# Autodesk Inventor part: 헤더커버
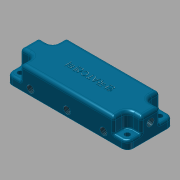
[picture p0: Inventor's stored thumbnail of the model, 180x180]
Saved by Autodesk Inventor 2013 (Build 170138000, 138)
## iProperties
Created: 2015-11
Part Number: 헤더커버
Material: 알루미늄 6061
Document SubType Name: Modeling
Designer: mduedu
Density: 2.71 g/cm^3
Mass: 171.744 g
Surface Area: 160.864 cm^2
Volume: 63.3741 cm^3
Author: mduedu
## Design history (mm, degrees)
sketch "스케치1"
  geometry: L1 (52.5, 20)-(-52.5, 20); L2 (-52.5, 20)-(-52.5, -20); L3 (-52.5, -20)-(52.5, -20); L4 (52.5, -20)-(52.5, 20); L5 (52.5, 20)-(-52.5, -20); L6 (-52.5, 20)-(52.5, -20); 1 further point
  constraints: 12 end point, 2 midpoint, 2 parallel, 1 horizontal, 1 perpendicular
  dimensions: "d0" = 105 distance of L3.end L2.end; "d1" = 40 distance of L2.end L1.end
extrude "돌출1" new body sketch "스케치1" distance "d2" = 20; taper "d3" = 0 deg
sketch "스케치2"
  geometry: L1 (-52.5, -20)-(-52.5, 20) reference; L2 (-52.5, 20)-(52.5, 20) reference; L3 (52.5, 20)-(52.5, -20) reference; L4 (52.5, -20)-(-52.5, -20) reference; L5 (-52.5, 20)-(-40.5, 20); L6 (-40.5, 20)-(-40.5, 8); L7 (-40.5, 8)-(-52.5, 8); L8 (-52.5, 8)-(-52.5, 20); L9 (52.5, 20)-(40.5, 20); L10 (40.5, 20)-(40.5, 8); L11 (40.5, 8)-(52.5, 8); L12 (52.5, 8)-(52.5, 20); L13 (52.5, -20)-(40.5, -20); L14 (40.5, -20)-(40.5, -8); L15 (40.5, -8)-(52.5, -8); L16 (52.5, -8)-(52.5, -20); L17 (-52.5, -20)-(-40.5, -20); L18 (-40.5, -20)-(-40.5, -8); L19 (-40.5, -8)-(-52.5, -8); L20 (-52.5, -8)-(-52.5, -20); 1 further point
  constraints: 32 end point, 8 parallel, 6 equal length, 4 horizontal, 4 perpendicular
  dimensions: "d4" = 12 distance of L6.end L7.end; "d5" = 12 distance of L5.end L6.end
extrude "돌출2" cut sketch "스케치2" distance "d6" = 13; taper "d7" = 0 deg
fillet "모깎기1" dims "d8" = 5
fillet "모깎기2" dims "d9" = 1
fillet "모깎기3" dims "d10" = 5
fillet "모깎기4" dims "d11" = 2
fillet "모깎기5" dims "d12" = 3
sketch "스케치3"
  geometry: L1 (-46.5, -14)-(46.5, -14); L2 (46.5, -14)-(46.5, 14); L3 (46.5, 14)-(-46.5, 14); L4 (-46.5, 14)-(-46.5, -14); L5 (-46.5, -14)-(46.5, 14); L6 (46.5, -14)-(-46.5, 14); L7 (47.5, 20)-(-47.5, 20) reference; L8 (52.5, -15)-(52.5, 15) reference; 5 further points
  constraints: 12 end point, 4 coincident, 2 midpoint, 2 parallel, 1 horizontal, 1 perpendicular
  dimensions: "d13" = 6 distance between parallel lines of L3 L7; "d14" = 6 distance between parallel lines of L2 L8
hole "구멍1" sketch "스케치3" at (-46.5, 14), (46.5, 14), (46.5, -14), (-46.5, -14) diameter "d15" = 4.5; stored, may be unused: countersink angle "d19" = 90 deg, drill point angle "d21" = 118 deg; dims "d16" = 6, "d17" = 4, "d18" = 2, "d20" = 8
sketch "스케치4"
  geometry: L1 (47.5, -20)-(-47.5, -20) reference; L2 (52.5, 15)-(52.5, -15) reference; L3 (-47.5, 20)-(47.5, 20) reference; L4 (-52.5, -15)-(-52.5, 15) reference; L5 (-52.5, 0)-(52.5, 0); C1 r 12.25 at (0, 0); C2 r 2.25 at (46.5, 14) reference; C3 r 2.25 at (-46.5, -14) reference; C4 r 2.25 at (46.5, -14) reference; C5 r 2.25 at (-46.5, 14) reference; C6 r 12.25 at (-32, 0); C7 r 12.25 at (32, 0); A1 r 5 centre (-47.5, -15) between (-52.5, -15) and (-47.5, -20) reference; A2 r 5 centre (47.5, -15) between (47.5, -20) and (52.5, -15) reference; A3 r 5 centre (47.5, 15) between (52.5, 15) and (47.5, 20) reference; A4 r 5 centre (-47.5, 15) between (-47.5, 20) and (-52.5, 15) reference; 1 further point
  constraints: 3 centre point, 2 end point, 2 midpoint, 2 point on line, 1 coincident
  dimensions: "d22" = 24.5 diameter of C1; "d23" = 24.5 diameter of C7 (= d22); "d24" = 24.5 diameter of C6 (= d22); "d25" = 32 distance of point (0, 0) C6.centre; "d26" = 32 distance of C7.centre point (0, 0) (= d25)
extrude "돌출3" cut sketch "스케치4" distance "d27" = 8; taper "d28" = 0 deg
fillet "모깎기6" dims "d29" = 5
sketch "스케치5"
  geometry: L1 (-52.5, 12)-(-47.119, 12); L2 (-40.191, 8)-(-37.635, 3.574); L3 (-52.5, 17)-(-52.5, 8) reference; L4 (-47.5, 0)-(-52.5, 0) reference; L5 (37.5, 20)-(-37.5, 20) reference; L6 (0, 0)-(0, 20); L7 (52.5, 12)-(47.119, 12); L8 (40.191, 8)-(37.635, 3.574); A1 r 8 centre (-47.119, 4) between (-40.191, 8) and (-47.119, 12); A2 r 8 centre (47.119, 4) between (47.119, 12) and (40.191, 8); 1 further point
  constraints: 10 end point, 5 symmetric about line, 4 point on circle, 3 point on line, 2 centre point, 2 tangent, 1 horizontal, 1 midpoint, 1 other
  dimensions: "d30" = 10 distance of L1.start point (-42.5, 12); "d32" = 120 deg angle of L2 L1; "d34" = 12 distance between parallel lines of L1 L4; "d35" = 8 radius of A1
sketch "스케치6"
  geometry: L1 (20, -5)-(20, 5) reference; L2 (8, -20)-(17, -20) reference; L3 (12, -20)-(12, -14.619); L4 (8, -7.691)-(3.81, -5.272); L5 (0, -20)-(0, -15) reference; A1 r 8 centre (4, -14.619) between (12, -14.619) and (8, -7.691); 2 further points
  constraints: 4 end point, 3 point on line, 2 point on circle, 2 tangent, 1 centre point, 1 perpendicular
  dimensions: "d36" = 10 distance of L3.start point (12, -10); "d38" = 12 distance between parallel lines of L3 L5; "d39" = 120 deg angle of L3 L4; "d40" = 8 radius of A1
node "작업점1"
node "작업점2"
node "작업점3"
hole "구멍2" diameter "d43" = 5.944; stored, may be unused: countersink angle "d49" = 90 deg, drill point angle "d51" = 0 deg; dims "d41" = 10, "d42" = 10, "d44" = 6.886, "d45" = 0.62479, "d46" = 5.959, "d47" = 4, "d48" = 2, "d50" = 6.9
hole "구멍3" diameter "d54" = 5.944; stored, may be unused: countersink angle "d60" = 90 deg, drill point angle "d62" = 0 deg; dims "d52" = 10, "d53" = 10, "d55" = 6.886, "d56" = 0.62479, "d57" = 5.959, "d58" = 4, "d59" = 2, "d61" = 6.9
hole "구멍4" diameter "d65" = 5.944; stored, may be unused: countersink angle "d71" = 90 deg, drill point angle "d73" = 0 deg; dims "d63" = 10, "d64" = 10, "d66" = 6.886, "d67" = 0.62479, "d68" = 5.959, "d69" = 4, "d70" = 2, "d72" = 6.9
sketch "스케치7"
  geometry: C1 r 2.972 at (15, 12) reference; 1 further point
sketch "스케치8"
  geometry: C1 r 2.972 at (15, 12) reference; 1 further point
sketch "스케치9"
  geometry: C1 r 2.972 at (47.5, 12) reference; 1 further point
feature "스윕1" dims "d74" = 0
feature "스윕2" dims "d75" = 0
feature "스윕3" dims "d76" = 0
sketch "스케치10"
  geometry: L1 (0, 0)-(95, 0) reference; L2 (22.75, 8)-(8.768, 8) reference; L3 (54.75, 8)-(40.25, 8) reference; L4 (86.232, 8)-(72.25, 8) reference; L5 (15.759, 8)-(15.759, 0); L6 (47.5, 8)-(47.5, 0); L7 (79.241, 8)-(79.241, 0); 5 further points
  constraints: 6 end point, 5 point on line, 3 midpoint, 2 horizontal alignment, 2 perpendicular, 1 parallel
  dimensions: "d77" = 5 distance from line of point (15.759, 5) L1
hole "구멍5" sketch "스케치10" at (15.759, 5), (47.5, 5), (79.241, 5) diameter "d78" = 5.944; stored, may be unused: countersink angle "d84" = 90 deg, drill point angle "d86" = 0 deg; dims "d79" = 6.886, "d80" = 0.62479, "d81" = 5.959, "d82" = 4, "d83" = 2, "d85" = 6.9
sketch "스케치11"
  geometry: C1 r 2.972 at (0, 0) reference; C2 r 2.972 at (31.741, 0) reference; C3 r 2.972 at (63.482, 0) reference; 1 further point
extrude "돌출4" cut sketch "스케치11" distance "d87" = 8; taper "d88" = 0 deg
sketch "스케치12"
  geometry: 2 further points
  constraints: 1 coincident, 1 other
feature "엠보싱1" sketch "스케치12" dims "d0" = 105, "d1" = 40, "d4" = 12, "d5" = 12, "d89" = 0.5, "d90" = 0
node "솔리드1"
node "투영된 루프1"
node "절단 모서리 투영1"
